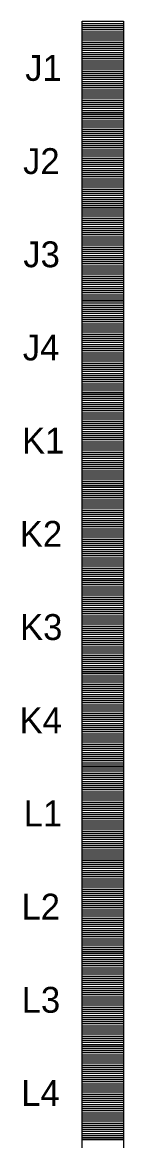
# Model space of a CAD drawing. Extents: x -124 to 80, y -10800 to 19.
# Drawn here: x -116 to 80, y -8642 to -6482 of the extents above; entities that cross this region are included whole.
import ezdxf

# ---------------------------------------------------------------- set-up
doc = ezdxf.new("R2010")
doc.units = 0
for name, color, linetype in [('Scratch_Level_1', 7, 'Continuous'), ('Scratch_Level_3', 7, 'Continuous'), ('Sheet Clip Boundary CELL', 7, 'Continuous')]:
    doc.layers.add(name, color=color, linetype=linetype)

msp = doc.modelspace()

# ---------------------------------------------------------------- linework, layer by layer
at = {"layer": 'Scratch_Level_1'}
for p, q in [((0, -6484), (80, -6484)), ((0, -6488), (80, -6488)), ((0, -6492), (80, -6492)), ((0, -6496), (80, -6496)), ((0, -6500), (80, -6500)), ((0, -6504), (80, -6504)), ((0, -6508), (80, -6508)), ((0, -6512), (80, -6512)), ((0, -6516), (80, -6516)), ((0, -6520), (80, -6520)), ((0, -6524), (80, -6524)), ((0, -6528), (80, -6528)), ((0, -6532), (80, -6532)), ((0, -6536), (80, -6536)), ((0, -6540), (80, -6540)), ((0, -6544), (80, -6544)), ((0, -6548), (80, -6548)), ((0, -6552), (80, -6552)), ((0, -6556), (80, -6556)), ((0, -6560), (80, -6560)), ((0, -6564), (80, -6564)), ((0, -6568), (80, -6568)), ((0, -6572), (80, -6572)), ((0, -6576), (80, -6576)), ((0, -6580), (80, -6580)), ((0, -6584), (80, -6584)), ((0, -6588), (80, -6588)), ((0, -6592), (80, -6592)), ((0, -6596), (80, -6596)), ((0, -6600), (80, -6600)), ((0, -6604), (80, -6604)), ((0, -6608), (80, -6608)), ((0, -6612), (80, -6612)), ((0, -6616), (80, -6616)), ((0, -6620), (80, -6620)), ((0, -6624), (80, -6624)), ((0, -6628), (80, -6628)), ((0, -6632), (80, -6632)), ((0, -6636), (80, -6636)), ((0, -6640), (80, -6640)), ((0, -6644), (80, -6644)), ((0, -6648), (80, -6648)), ((0, -6652), (80, -6652)), ((0, -6656), (80, -6656)), ((0, -6660), (80, -6660)), ((0, -6660), (80, -6660)), ((0, -6664), (80, -6664)), ((0, -6668), (80, -6668)), ((0, -6672), (80, -6672)), ((0, -6676), (80, -6676)), ((0, -6680), (80, -6680)), ((0, -6684), (80, -6684)), ((0, -6688), (80, -6688)), ((0, -6692), (80, -6692)), ((0, -6696), (80, -6696)), ((0, -6700), (80, -6700)), ((0, -6704), (80, -6704)), ((0, -6708), (80, -6708)), ((0, -6712), (80, -6712)), ((0, -6716), (80, -6716)), ((0, -6720), (80, -6720)), ((0, -6724), (80, -6724)), ((0, -6728), (80, -6728)), ((0, -6732), (80, -6732)), ((0, -6736), (80, -6736)), ((0, -6740), (80, -6740)), ((0, -6744), (80, -6744)), ((0, -6748), (80, -6748)), ((0, -6752), (80, -6752)), ((0, -6756), (80, -6756)), ((0, -6760), (80, -6760)), ((0, -6764), (80, -6764)), ((0, -6768), (80, -6768)), ((0, -6772), (80, -6772)), ((0, -6776), (80, -6776)), ((0, -6780), (80, -6780)), ((0, -6784), (80, -6784)), ((0, -6788), (80, -6788)), ((0, -6792), (80, -6792)), ((0, -6796), (80, -6796)), ((0, -6800), (80, -6800)), ((0, -6804), (80, -6804)), ((0, -6808), (80, -6808)), ((0, -6812), (80, -6812)), ((0, -6816), (80, -6816)), ((0, -6820), (80, -6820)), ((0, -6824), (80, -6824)), ((0, -6828), (80, -6828)), ((0, -6832), (80, -6832)), ((0, -6836), (80, -6836)), ((0, -6840), (80, -6840)), ((0, -6840), (80, -6840)), ((0, -6844), (80, -6844)), ((0, -6848), (80, -6848)), ((0, -6852), (80, -6852)), ((0, -6856), (80, -6856)), ((0, -6860), (80, -6860)), ((0, -6864), (80, -6864)), ((0, -6868), (80, -6868)), ((0, -6872), (80, -6872)), ((0, -6876), (80, -6876)), ((0, -6880), (80, -6880)), ((0, -6884), (80, -6884)), ((0, -6888), (80, -6888)), ((0, -6892), (80, -6892)), ((0, -6896), (80, -6896)), ((0, -6900), (80, -6900)), ((0, -6904), (80, -6904)), ((0, -6908), (80, -6908)), ((0, -6912), (80, -6912)), ((0, -6916), (80, -6916)), ((0, -6920), (80, -6920)), ((0, -6924), (80, -6924)), ((0, -6928), (80, -6928)), ((0, -6932), (80, -6932)), ((0, -6936), (80, -6936)), ((0, -6940), (80, -6940)), ((0, -6944), (80, -6944)), ((0, -6948), (80, -6948)), ((0, -6952), (80, -6952)), ((0, -6956), (80, -6956)), ((0, -6960), (80, -6960)), ((0, -6964), (80, -6964)), ((0, -6968), (80, -6968)), ((0, -6972), (80, -6972)), ((0, -6976), (80, -6976)), ((0, -6980), (80, -6980)), ((0, -6984), (80, -6984)), ((0, -6988), (80, -6988)), ((0, -6992), (80, -6992)), ((0, -6996), (80, -6996)), ((0, -7000), (80, -7000)), ((0, -7004), (80, -7004)), ((0, -7008), (80, -7008)), ((0, -7012), (80, -7012)), ((0, -7016), (80, -7016)), ((0, -7020), (80, -7020)), ((0, -7020), (80, -7020)), ((0, -7024), (80, -7024)), ((0, -7028), (80, -7028)), ((0, -7032), (80, -7032)), ((0, -7036), (80, -7036)), ((0, -7040), (80, -7040)), ((0, -7044), (80, -7044)), ((0, -7048), (80, -7048)), ((0, -7052), (80, -7052)), ((0, -7056), (80, -7056)), ((0, -7060), (80, -7060)), ((0, -7064), (80, -7064)), ((0, -7068), (80, -7068)), ((0, -7072), (80, -7072)), ((0, -7076), (80, -7076)), ((0, -7080), (80, -7080)), ((0, -7084), (80, -7084)), ((0, -7088), (80, -7088)), ((0, -7092), (80, -7092)), ((0, -7096), (80, -7096)), ((0, -7100), (80, -7100)), ((0, -7104), (80, -7104)), ((0, -7108), (80, -7108)), ((0, -7112), (80, -7112)), ((0, -7116), (80, -7116)), ((0, -7120), (80, -7120)), ((0, -7124), (80, -7124)), ((0, -7128), (80, -7128)), ((0, -7132), (80, -7132)), ((0, -7136), (80, -7136)), ((0, -7140), (80, -7140)), ((0, -7144), (80, -7144)), ((0, -7148), (80, -7148)), ((0, -7152), (80, -7152)), ((0, -7156), (80, -7156)), ((0, -7160), (80, -7160)), ((0, -7164), (80, -7164)), ((0, -7168), (80, -7168)), ((0, -7172), (80, -7172)), ((0, -7176), (80, -7176)), ((0, -7180), (80, -7180)), ((0, -7184), (80, -7184)), ((0, -7188), (80, -7188)), ((0, -7192), (80, -7192)), ((0, -7196), (80, -7196)), ((0, -7200), (80, -7200)), ((0, -7200), (80, -7200)), ((0, -7204), (80, -7204)), ((0, -7208), (80, -7208)), ((0, -7212), (80, -7212)), ((0, -7216), (80, -7216)), ((0, -7220), (80, -7220)), ((0, -7224), (80, -7224)), ((0, -7228), (80, -7228)), ((0, -7232), (80, -7232)), ((0, -7236), (80, -7236)), ((0, -7240), (80, -7240)), ((0, -7244), (80, -7244)), ((0, -7248), (80, -7248)), ((0, -7252), (80, -7252)), ((0, -7256), (80, -7256)), ((0, -7260), (80, -7260)), ((0, -7264), (80, -7264)), ((0, -7268), (80, -7268)), ((0, -7272), (80, -7272)), ((0, -7276), (80, -7276)), ((0, -7280), (80, -7280)), ((0, -7284), (80, -7284)), ((0, -7288), (80, -7288)), ((0, -7292), (80, -7292)), ((0, -7296), (80, -7296)), ((0, -7300), (80, -7300)), ((0, -7304), (80, -7304)), ((0, -7308), (80, -7308)), ((0, -7312), (80, -7312)), ((0, -7316), (80, -7316)), ((0, -7320), (80, -7320)), ((0, -7324), (80, -7324)), ((0, -7328), (80, -7328)), ((0, -7332), (80, -7332)), ((0, -7336), (80, -7336)), ((0, -7340), (80, -7340)), ((0, -7344), (80, -7344)), ((0, -7348), (80, -7348)), ((0, -7352), (80, -7352)), ((0, -7356), (80, -7356)), ((0, -7360), (80, -7360)), ((0, -7364), (80, -7364)), ((0, -7368), (80, -7368)), ((0, -7372), (80, -7372)), ((0, -7376), (80, -7376)), ((0, -7380), (80, -7380)), ((0, -7380), (80, -7380)), ((0, -7384), (80, -7384)), ((0, -7388), (80, -7388)), ((0, -7392), (80, -7392)), ((0, -7396), (80, -7396)), ((0, -7400), (80, -7400)), ((0, -7404), (80, -7404)), ((0, -7408), (80, -7408)), ((0, -7412), (80, -7412)), ((0, -7416), (80, -7416)), ((0, -7420), (80, -7420)), ((0, -7424), (80, -7424)), ((0, -7428), (80, -7428)), ((0, -7432), (80, -7432)), ((0, -7436), (80, -7436)), ((0, -7440), (80, -7440)), ((0, -7444), (80, -7444)), ((0, -7448), (80, -7448)), ((0, -7452), (80, -7452)), ((0, -7456), (80, -7456)), ((0, -7460), (80, -7460)), ((0, -7464), (80, -7464)), ((0, -7468), (80, -7468)), ((0, -7472), (80, -7472)), ((0, -7476), (80, -7476)), ((0, -7480), (80, -7480)), ((0, -7484), (80, -7484)), ((0, -7488), (80, -7488)), ((0, -7492), (80, -7492)), ((0, -7496), (80, -7496)), ((0, -7500), (80, -7500)), ((0, -7504), (80, -7504)), ((0, -7508), (80, -7508)), ((0, -7512), (80, -7512)), ((0, -7516), (80, -7516)), ((0, -7520), (80, -7520)), ((0, -7524), (80, -7524)), ((0, -7528), (80, -7528)), ((0, -7532), (80, -7532)), ((0, -7536), (80, -7536)), ((0, -7540), (80, -7540)), ((0, -7544), (80, -7544)), ((0, -7548), (80, -7548)), ((0, -7552), (80, -7552)), ((0, -7556), (80, -7556)), ((0, -7560), (80, -7560)), ((0, -7560), (80, -7560)), ((0, -7564), (80, -7564)), ((0, -7568), (80, -7568)), ((0, -7572), (80, -7572)), ((0, -7576), (80, -7576)), ((0, -7580), (80, -7580)), ((0, -7584), (80, -7584)), ((0, -7588), (80, -7588)), ((0, -7592), (80, -7592)), ((0, -7596), (80, -7596)), ((0, -7600), (80, -7600)), ((0, -7604), (80, -7604)), ((0, -7608), (80, -7608)), ((0, -7612), (80, -7612)), ((0, -7616), (80, -7616)), ((0, -7620), (80, -7620)), ((0, -7624), (80, -7624)), ((0, -7628), (80, -7628)), ((0, -7632), (80, -7632)), ((0, -7636), (80, -7636)), ((0, -7640), (80, -7640)), ((0, -7644), (80, -7644)), ((0, -7648), (80, -7648)), ((0, -7652), (80, -7652)), ((0, -7656), (80, -7656)), ((0, -7660), (80, -7660)), ((0, -7664), (80, -7664)), ((0, -7668), (80, -7668)), ((0, -7672), (80, -7672)), ((0, -7676), (80, -7676)), ((0, -7680), (80, -7680)), ((0, -7684), (80, -7684)), ((0, -7688), (80, -7688)), ((0, -7692), (80, -7692)), ((0, -7696), (80, -7696)), ((0, -7700), (80, -7700)), ((0, -7704), (80, -7704)), ((0, -7708), (80, -7708)), ((0, -7712), (80, -7712)), ((0, -7716), (80, -7716)), ((0, -7720), (80, -7720)), ((0, -7724), (80, -7724)), ((0, -7728), (80, -7728)), ((0, -7732), (80, -7732)), ((0, -7736), (80, -7736)), ((0, -7740), (80, -7740)), ((0, -7740), (80, -7740)), ((0, -7744), (80, -7744)), ((0, -7748), (80, -7748)), ((0, -7752), (80, -7752)), ((0, -7756), (80, -7756)), ((0, -7760), (80, -7760)), ((0, -7764), (80, -7764)), ((0, -7768), (80, -7768)), ((0, -7772), (80, -7772)), ((0, -7776), (80, -7776)), ((0, -7780), (80, -7780)), ((0, -7784), (80, -7784)), ((0, -7788), (80, -7788)), ((0, -7792), (80, -7792)), ((0, -7796), (80, -7796)), ((0, -7800), (80, -7800)), ((0, -7804), (80, -7804)), ((0, -7808), (80, -7808)), ((0, -7812), (80, -7812)), ((0, -7816), (80, -7816)), ((0, -7820), (80, -7820)), ((0, -7824), (80, -7824)), ((0, -7828), (80, -7828)), ((0, -7832), (80, -7832)), ((0, -7836), (80, -7836)), ((0, -7840), (80, -7840)), ((0, -7844), (80, -7844)), ((0, -7848), (80, -7848)), ((0, -7852), (80, -7852)), ((0, -7856), (80, -7856)), ((0, -7860), (80, -7860)), ((0, -7864), (80, -7864)), ((0, -7868), (80, -7868)), ((0, -7872), (80, -7872)), ((0, -7876), (80, -7876)), ((0, -7880), (80, -7880)), ((0, -7884), (80, -7884)), ((0, -7888), (80, -7888)), ((0, -7892), (80, -7892)), ((0, -7896), (80, -7896)), ((0, -7900), (80, -7900)), ((0, -7904), (80, -7904)), ((0, -7908), (80, -7908)), ((0, -7912), (80, -7912)), ((0, -7916), (80, -7916)), ((0, -7920), (80, -7920)), ((0, -7920), (80, -7920)), ((0, -7924), (80, -7924)), ((0, -7928), (80, -7928)), ((0, -7932), (80, -7932)), ((0, -7936), (80, -7936)), ((0, -7940), (80, -7940)), ((0, -7944), (80, -7944)), ((0, -7948), (80, -7948)), ((0, -7952), (80, -7952)), ((0, -7956), (80, -7956)), ((0, -7960), (80, -7960)), ((0, -7964), (80, -7964)), ((0, -7968), (80, -7968)), ((0, -7972), (80, -7972)), ((0, -7976), (80, -7976)), ((0, -7980), (80, -7980)), ((0, -7984), (80, -7984)), ((0, -7988), (80, -7988)), ((0, -7992), (80, -7992)), ((0, -7996), (80, -7996)), ((0, -8000), (80, -8000)), ((0, -8004), (80, -8004)), ((0, -8008), (80, -8008)), ((0, -8012), (80, -8012)), ((0, -8016), (80, -8016)), ((0, -8020), (80, -8020)), ((0, -8024), (80, -8024)), ((0, -8028), (80, -8028)), ((0, -8032), (80, -8032)), ((0, -8036), (80, -8036)), ((0, -8040), (80, -8040)), ((0, -8044), (80, -8044)), ((0, -8048), (80, -8048)), ((0, -8052), (80, -8052)), ((0, -8056), (80, -8056)), ((0, -8060), (80, -8060)), ((0, -8064), (80, -8064)), ((0, -8068), (80, -8068)), ((0, -8072), (80, -8072)), ((0, -8076), (80, -8076)), ((0, -8080), (80, -8080)), ((0, -8084), (80, -8084)), ((0, -8088), (80, -8088)), ((0, -8092), (80, -8092)), ((0, -8096), (80, -8096)), ((0, -8096), (80, -8096)), ((0, -8100), (80, -8100)), ((0, -8100), (80, -8100)), ((0, -8104), (80, -8104)), ((0, -8108), (80, -8108)), ((0, -8112), (80, -8112)), ((0, -8116), (80, -8116)), ((0, -8120), (80, -8120)), ((0, -8124), (80, -8124)), ((0, -8128), (80, -8128)), ((0, -8132), (80, -8132)), ((0, -8136), (80, -8136)), ((0, -8140), (80, -8140)), ((0, -8144), (80, -8144)), ((0, -8148), (80, -8148)), ((0, -8152), (80, -8152)), ((0, -8156), (80, -8156)), ((0, -8160), (80, -8160)), ((0, -8164), (80, -8164)), ((0, -8168), (80, -8168)), ((0, -8172), (80, -8172)), ((0, -8176), (80, -8176)), ((0, -8180), (80, -8180)), ((0, -8184), (80, -8184)), ((0, -8188), (80, -8188)), ((0, -8192), (80, -8192)), ((0, -8196), (80, -8196)), ((0, -8200), (80, -8200)), ((0, -8204), (80, -8204)), ((0, -8208), (80, -8208)), ((0, -8212), (80, -8212)), ((0, -8216), (80, -8216)), ((0, -8220), (80, -8220)), ((0, -8224), (80, -8224)), ((0, -8228), (80, -8228)), ((0, -8232), (80, -8232)), ((0, -8236), (80, -8236)), ((0, -8240), (80, -8240)), ((0, -8244), (80, -8244)), ((0, -8248), (80, -8248)), ((0, -8252), (80, -8252)), ((0, -8256), (80, -8256)), ((0, -8260), (80, -8260)), ((0, -8264), (80, -8264)), ((0, -8268), (80, -8268)), ((0, -8272), (80, -8272)), ((0, -8276), (80, -8276)), ((0, -8276), (80, -8276)), ((0, -8280), (80, -8280)), ((0, -8284), (80, -8284)), ((0, -8288), (80, -8288)), ((0, -8292), (80, -8292)), ((0, -8296), (80, -8296)), ((0, -8300), (80, -8300)), ((0, -8304), (80, -8304)), ((0, -8308), (80, -8308)), ((0, -8312), (80, -8312)), ((0, -8316), (80, -8316)), ((0, -8320), (80, -8320)), ((0, -8324), (80, -8324)), ((0, -8328), (80, -8328)), ((0, -8332), (80, -8332)), ((0, -8336), (80, -8336)), ((0, -8340), (80, -8340)), ((0, -8344), (80, -8344)), ((0, -8348), (80, -8348)), ((0, -8352), (80, -8352)), ((0, -8356), (80, -8356)), ((0, -8360), (80, -8360)), ((0, -8364), (80, -8364)), ((0, -8368), (80, -8368)), ((0, -8372), (80, -8372)), ((0, -8376), (80, -8376)), ((0, -8380), (80, -8380)), ((0, -8384), (80, -8384)), ((0, -8388), (80, -8388)), ((0, -8392), (80, -8392)), ((0, -8396), (80, -8396)), ((0, -8400), (80, -8400)), ((0, -8404), (80, -8404)), ((0, -8408), (80, -8408)), ((0, -8412), (80, -8412)), ((0, -8416), (80, -8416)), ((0, -8420), (80, -8420)), ((0, -8424), (80, -8424)), ((0, -8428), (80, -8428)), ((0, -8432), (80, -8432)), ((0, -8436), (80, -8436)), ((0, -8440), (80, -8440)), ((0, -8444), (80, -8444)), ((0, -8448), (80, -8448)), ((0, -8452), (80, -8452)), ((0, -8456), (80, -8456)), ((0, -8456), (80, -8456)), ((0, -8460), (80, -8460)), ((0, -8464), (80, -8464)), ((0, -8468), (80, -8468)), ((0, -8472), (80, -8472)), ((0, -8476), (80, -8476)), ((0, -8480), (80, -8480)), ((0, -8484), (80, -8484)), ((0, -8488), (80, -8488)), ((0, -8492), (80, -8492)), ((0, -8496), (80, -8496)), ((0, -8500), (80, -8500)), ((0, -8504), (80, -8504)), ((0, -8508), (80, -8508)), ((0, -8512), (80, -8512)), ((0, -8516), (80, -8516)), ((0, -8520), (80, -8520)), ((0, -8524), (80, -8524)), ((0, -8528), (80, -8528)), ((0, -8532), (80, -8532)), ((0, -8536), (80, -8536)), ((0, -8540), (80, -8540)), ((0, -8544), (80, -8544)), ((0, -8548), (80, -8548)), ((0, -8552), (80, -8552)), ((0, -8556), (80, -8556)), ((0, -8560), (80, -8560)), ((0, -8564), (80, -8564)), ((0, -8568), (80, -8568)), ((0, -8572), (80, -8572)), ((0, -8576), (80, -8576)), ((0, -8580), (80, -8580)), ((0, -8584), (80, -8584)), ((0, -8588), (80, -8588)), ((0, -8592), (80, -8592)), ((0, -8596), (80, -8596)), ((0, -8600), (80, -8600)), ((0, -8604), (80, -8604)), ((0, -8608), (80, -8608)), ((0, -8612), (80, -8612)), ((0, -8616), (80, -8616)), ((0, -8620), (80, -8620)), ((0, -8624), (80, -8624)), ((0, -8628), (80, -8628)), ((0, -8632), (80, -8632)), ((0, -8632), (80, -8632)), ((0, -8636), (80, -8636)), ((0, -8636), (80, -8636)), ((0, -8640), (80, -8640))]:
    msp.add_line(p, q, dxfattribs=at)
at = {"layer": 'Sheet Clip Boundary CELL'}
for points in [[(0, -6480), (80, -6480), (80, -6660), (0, -6660)], [(0, -6660), (80, -6660), (80, -6840), (0, -6840)], [(0, -6840), (80, -6840), (80, -7020), (0, -7020)], [(0, -7020), (80, -7020), (80, -7200), (0, -7200)], [(0, -7200), (80, -7200), (80, -7380), (0, -7380)], [(0, -7380), (80, -7380), (80, -7560), (0, -7560)], [(0, -7560), (80, -7560), (80, -7740), (0, -7740)], [(0, -7740), (80, -7740), (80, -7920), (0, -7920)], [(0, -7920), (80, -7920), (80, -8100), (0, -8100)], [(0, -8100), (80, -8100), (80, -8280), (0, -8280)], [(0, -8280), (80, -8280), (80, -8460), (0, -8460)], [(0, -8460), (80, -8460), (80, -8640), (0, -8640)], [(0, -8640), (80, -8640), (80, -8820), (0, -8820)]]:
    msp.add_lwpolyline(points, close=True, dxfattribs=at)

# ---------------------------------------------------------------- texts
at = {"layer": 'Scratch_Level_3'}
for s, p in [('J1', (-110.2, -6595)), ('J2', (-114.3, -6775)), ('J3', (-113.9, -6955)), ('J4', (-114.9, -7135)), ('K1', (-116.4, -7315)), ('K2', (-120.6, -7495)), ('K3', (-120.2, -7675)), ('K4', (-121.2, -7855)), ('L1', (-113.2, -8035)), ('L2', (-117.4, -8215)), ('L3', (-117, -8395)), ('L4', (-118, -8575))]:
    msp.add_text(s, height=50, dxfattribs=at).set_placement(p)

doc.saveas('drawing.dxf')
